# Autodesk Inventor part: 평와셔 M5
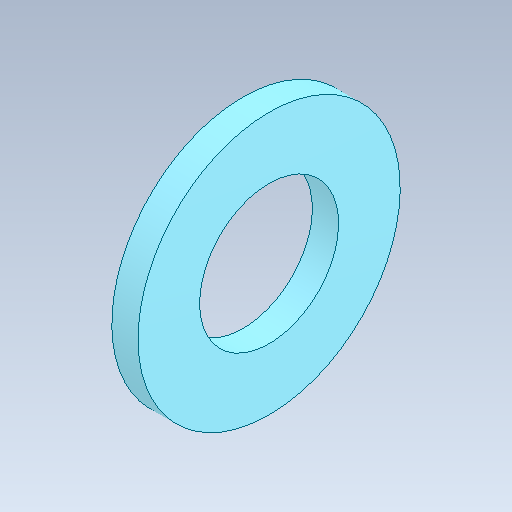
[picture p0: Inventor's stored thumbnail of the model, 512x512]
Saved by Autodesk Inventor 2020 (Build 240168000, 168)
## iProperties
Created: 2024-09
Part Number: 평와셔 M5
Material: 강철, 연강
Description: 평면 와셔
Document SubType Name: Modeling
Designer: oem
Density: 7.85 g/cm^3
Appearance: 기본값
Author: jhkim
Sending System: Autodesk Inventor 2025
Preprocessor: ST-DEVELOPER v20
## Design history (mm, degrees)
feature "Solid1"
node "솔리드1"
